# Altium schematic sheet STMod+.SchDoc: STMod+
size A4; Author: P.A.; CompanyName: STMicroelectronics; Organization: Microcontrollers Division; Address1: 12, Rue Jules HOROWITZ; Address2: 38019 Grenoble; Address3: FRANCE; DocumentNumber: 7; Revision: C; SheetNumber: 7; SheetTotal: 16; Project: STM32L4S5AII6_IOT_V2
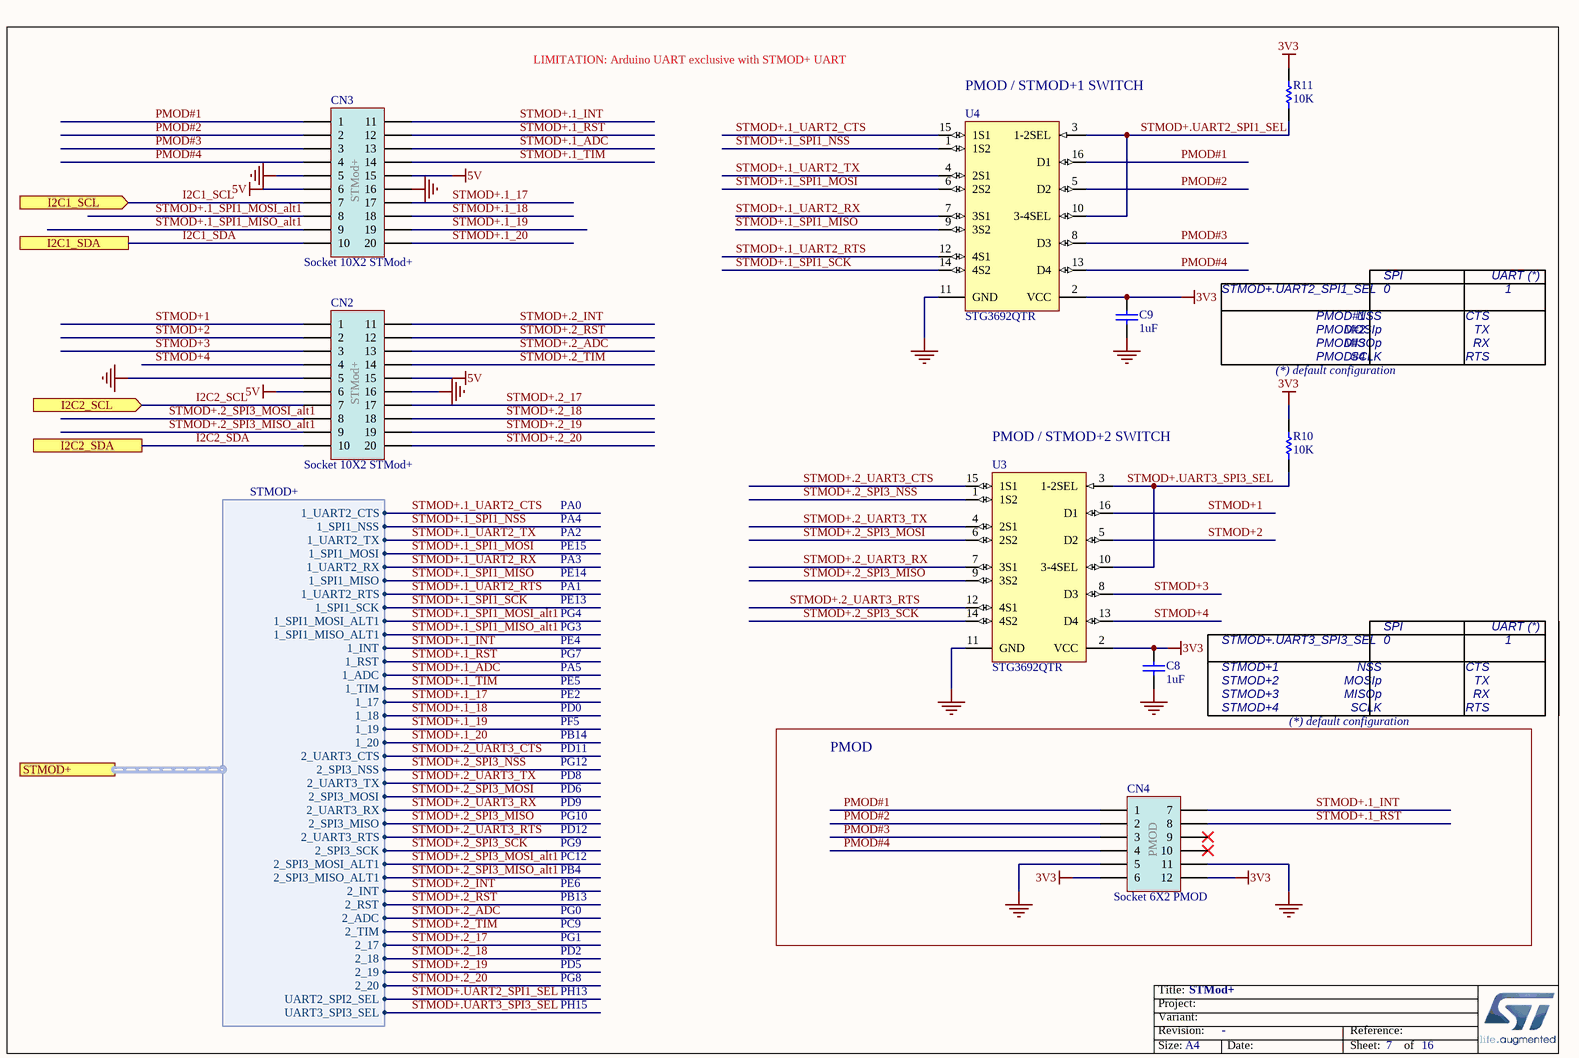
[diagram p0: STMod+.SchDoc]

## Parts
C8  value 1uF  [C0603]  (hidden comment: Capacitor)
C9  value 1uF  [C0603]  (hidden comment: Capacitor)
CN2  Socket 10X2 STMod+  [CON_SAMTEC_SQT-110-01-F-D-RA__STMOD+]
CN3  Socket 10X2 STMod+  [CON_SAMTEC_SQT-110-01-F-D-RA__STMOD+]
CN4  Socket 6X2 PMOD  [CON_SAMTEC_SSW-106-02-F-D-RA__PMOD]
R10  value 10K  [R0402]
R11  value 10K  [R0402]
U3  STG3692QTR  [ICC_UFQFN16-EPAD_2P6X1P8_P040]
U4  STG3692QTR  [ICC_UFQFN16-EPAD_2P6X1P8_P040]

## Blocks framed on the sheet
PMOD: CN4

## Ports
I2C1_SCL (in), I2C1_SDA, I2C2_SCL (in), I2C2_SDA, STMOD+ (harness STMOD+)

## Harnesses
STMOD+: 1_UART2_CTS, 1_SPI1_NSS, 1_UART2_TX, 1_SPI1_MOSI, 1_SPI1_MISO, 1_UART2_RTS, 1_ADC, 1_17, 1_18, 1_19, 1_20, 2_UART3_CTS, 2_SPI3_NSS, 2_UART3_TX, 2_SPI3_MOSI, 2_SPI3_MISO, 2_UART3_RTS, 2_UART3_RX, 1_UART2_RX, 1_SPI1_MOSI_ALT1, 2_SPI3_SCK, 2_SPI3_MOSI_ALT1, 1_SPI1_MISO_ALT1, 1_SPI1_SCK, 1_RST, 1_INT, 1_TIM, 2_SPI3_MISO_ALT1, 2_INT, 2_RST, 2_ADC, 2_TIM, 2_17, 2_18, 2_19, 2_20, UART2_SPI2_SEL, UART3_SPI3_SEL

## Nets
3V3: C8.2 C9.2 CN4.6 CN4.12 R10.2 R11.2 U3.2(VCC) U4.2(VCC)
5V: CN2.6 CN2.15 CN3.6 CN3.15
GND: C8.1 C9.1 CN2.5 CN2.16 CN3.5 CN3.16 CN4.5 CN4.11 U3.11(GND) U4.11(GND)
I2C1_SCL: CN3.7 ; port I2C1_SCL
I2C1_SDA: CN3.10 ; port I2C1_SDA
I2C2_SCL: CN2.7 ; port I2C2_SCL
I2C2_SDA: CN2.10 ; port I2C2_SDA
PMOD#1: CN3.1 CN4.1 U4.16(D1)
PMOD#2: CN3.2 CN4.2 U4.5(D2)
PMOD#3: CN3.3 CN4.3 U4.8(D3)
PMOD#4: CN3.4 CN4.4 U4.13(D4)
STMOD+1: CN2.1 U3.16(D1)
STMOD+2: CN2.2 U3.5(D2)
STMOD+3: CN2.3 U3.8(D3)
STMOD+4: CN2.4 U3.13(D4)
STMOD+.1_17: CN3.17 ; port STMOD+.1_17
STMOD+.1_18: CN3.18 ; port STMOD+.1_18
STMOD+.1_19: CN3.19 ; port STMOD+.1_19
STMOD+.1_20: CN3.20 ; port STMOD+.1_20
STMOD+.1_ADC: CN3.13 ; port STMOD+.1_ADC
STMOD+.1_INT: CN3.11 CN4.7 ; port STMOD+.1_INT
STMOD+.1_RST: CN3.12 CN4.8 ; port STMOD+.1_RST
STMOD+.1_SPI1_MISO: U4.9(3S2) ; port STMOD+.1_SPI1_MISO
STMOD+.1_SPI1_MISO_alt1: CN3.9 ; port STMOD+.1_SPI1_MISO_ALT1
STMOD+.1_SPI1_MOSI: U4.6(2S2) ; port STMOD+.1_SPI1_MOSI
STMOD+.1_SPI1_MOSI_alt1: CN3.8 ; port STMOD+.1_SPI1_MOSI_ALT1
STMOD+.1_SPI1_NSS: U4.1(1S2) ; port STMOD+.1_SPI1_NSS
STMOD+.1_SPI1_SCK: U4.14(4S2) ; port STMOD+.1_SPI1_SCK
STMOD+.1_TIM: CN3.14 ; port STMOD+.1_TIM
STMOD+.1_UART2_CTS: U4.15(1S1) ; port STMOD+.1_UART2_CTS
STMOD+.1_UART2_RTS: U4.12(4S1) ; port STMOD+.1_UART2_RTS
STMOD+.1_UART2_RX: U4.7(3S1) ; port STMOD+.1_UART2_RX
STMOD+.1_UART2_TX: U4.4(2S1) ; port STMOD+.1_UART2_TX
STMOD+.2_17: CN2.17 ; port STMOD+.2_17
STMOD+.2_18: CN2.18 ; port STMOD+.2_18
STMOD+.2_19: CN2.19 ; port STMOD+.2_19
STMOD+.2_20: CN2.20 ; port STMOD+.2_20
STMOD+.2_ADC: CN2.13 ; port STMOD+.2_ADC
STMOD+.2_INT: CN2.11 ; port STMOD+.2_INT
STMOD+.2_RST: CN2.12 ; port STMOD+.2_RST
STMOD+.2_SPI3_MISO: U3.9(3S2) ; port STMOD+.2_SPI3_MISO
STMOD+.2_SPI3_MISO_alt1: CN2.9 ; port STMOD+.2_SPI3_MISO_ALT1
STMOD+.2_SPI3_MOSI: U3.6(2S2) ; port STMOD+.2_SPI3_MOSI
STMOD+.2_SPI3_MOSI_alt1: CN2.8 ; port STMOD+.2_SPI3_MOSI_ALT1
STMOD+.2_SPI3_NSS: U3.1(1S2) ; port STMOD+.2_SPI3_NSS
STMOD+.2_SPI3_SCK: U3.14(4S2) ; port STMOD+.2_SPI3_SCK
STMOD+.2_TIM: CN2.14 ; port STMOD+.2_TIM
STMOD+.2_UART3_CTS: U3.15(1S1) ; port STMOD+.2_UART3_CTS
STMOD+.2_UART3_RTS: U3.12(4S1) ; port STMOD+.2_UART3_RTS
STMOD+.2_UART3_RX: U3.7(3S1) ; port STMOD+.2_UART3_RX
STMOD+.2_UART3_TX: U3.4(2S1) ; port STMOD+.2_UART3_TX
STMOD+.UART2_SPI1_SEL: R11.1 U4.3(1-2SEL) U4.10(3-4SEL) ; port STMOD+.UART2_SPI2_SEL
STMOD+.UART3_SPI3_SEL: R10.1 U3.3(1-2SEL) U3.10(3-4SEL) ; port STMOD+.UART3_SPI3_SEL

Not connected (* = marked no-connect by the designer): CN4 9* 10*

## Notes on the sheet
- LIMITATION: Arduino UART exclusive with STMOD+ UART
- (near U4) PMOD / STMOD+1 SWITCH
- STMOD+.UART2_SPI1_SEL
- PMOD#2
- PMOD#1
- 0
- MOSIp
- SPI
- NSS
- TX
- UART (*)
- CTS
- 1
- (*) default configuration
- PMOD#3
- PMOD#4
- MISOp
- SCLK
- RX
- RTS
- (near U3) PMOD / STMOD+2 SWITCH
- PA0
- PA4
- PA2
- PE14
- PA3
- PE15
- PA1
- PE13
- PG3
- PG4
- PE4
- PA5
- PG7
- STMOD+.UART3_SPI3_SEL
- STMOD+1
- PE5
- PE2
- PD0
- PF5
- PB14
- STMOD+2
- STMOD+3
- STMOD+4
- PD11
- PG12
- PD8
- PD9
- PD6
- PG10
- PD12
- PG9
- PC12
- PB4
- PE6
- PG0
- PC9
- PB13
- PG1
- PD2
- PG8
- PD5
- PH13
- PH15

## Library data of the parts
C8 C9 = MCD-00010: Capacitor, MLCC, 1uF, 16V, X5R, 10%, 0603, T=0,8mm; Manufacturer_Part_Number: CC0603KRX5R7BB105; Manufacturer: YAGEO; Provided_By: SUBCO; Initial_Board_Reference: MB1274; Item Type: Item; Path: ws/MCD_ApplicationBoards/Lists/MCDPARTSdatabase
CN2 CN3 = MCD-00309: Socket 10x2, 2.00mm, RA, TH, Height 6.35mm/2.29mm; Part_Type: Connector; Manufacturer_Part_Number: SQT-110-01-F-D-RA; Manufacturer: SAMTEC; Provided_By: SubCon; Initial_Board_Reference: MB1311
CN4 = MCD-00308: Socket, 6x2, 2.54mm, TH, RA, Height 8.51mm/7.62mm; Part_Type: Connector; Manufacturer_Part_Number: SSW-106-02-F-D-RA; Manufacturer: SAMTEC; Provided_By: Subcon; Initial_Board_Reference: MB1311
R10 R11 = MCD-00053: Resistor,10K,0402,1%,1/16W; Manufacturer_Part_Number: RC0402FR-0710KL; Manufacturer: YAGEO; Provided_By: subcon; Initial_Board_Reference: MB1274
U3 U4 = MCD-00317: Low voltage high bandwidth quad SPDT switch; Part_Type: IC; Manufacturer: STMICROELECTRONICS; Provided_By: SUBCO with ST control; Initial_Board_Reference: MB1311; Item Type: Item; Path: ws/MCD_ApplicationBoards/Lists/MCDPARTSdatabase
